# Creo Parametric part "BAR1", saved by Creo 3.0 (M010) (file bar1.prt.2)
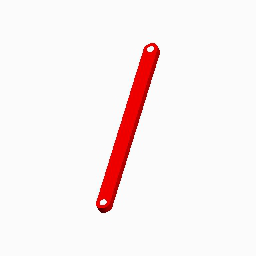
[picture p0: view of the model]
Units: millimeter Newton Second (mmNs); MM, TONNE, SECS

Created from: MMNS_PART_SOLID.PRT

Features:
  1. datum plane "RIGHT"
  2. datum plane "TOP"
  3. datum plane "FRONT"
  4. coordinate system
  5. sketch "Sketch 1"
  6. extrusion "Extrude 1"

Surfaces: 7 plane, 6 cylinder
